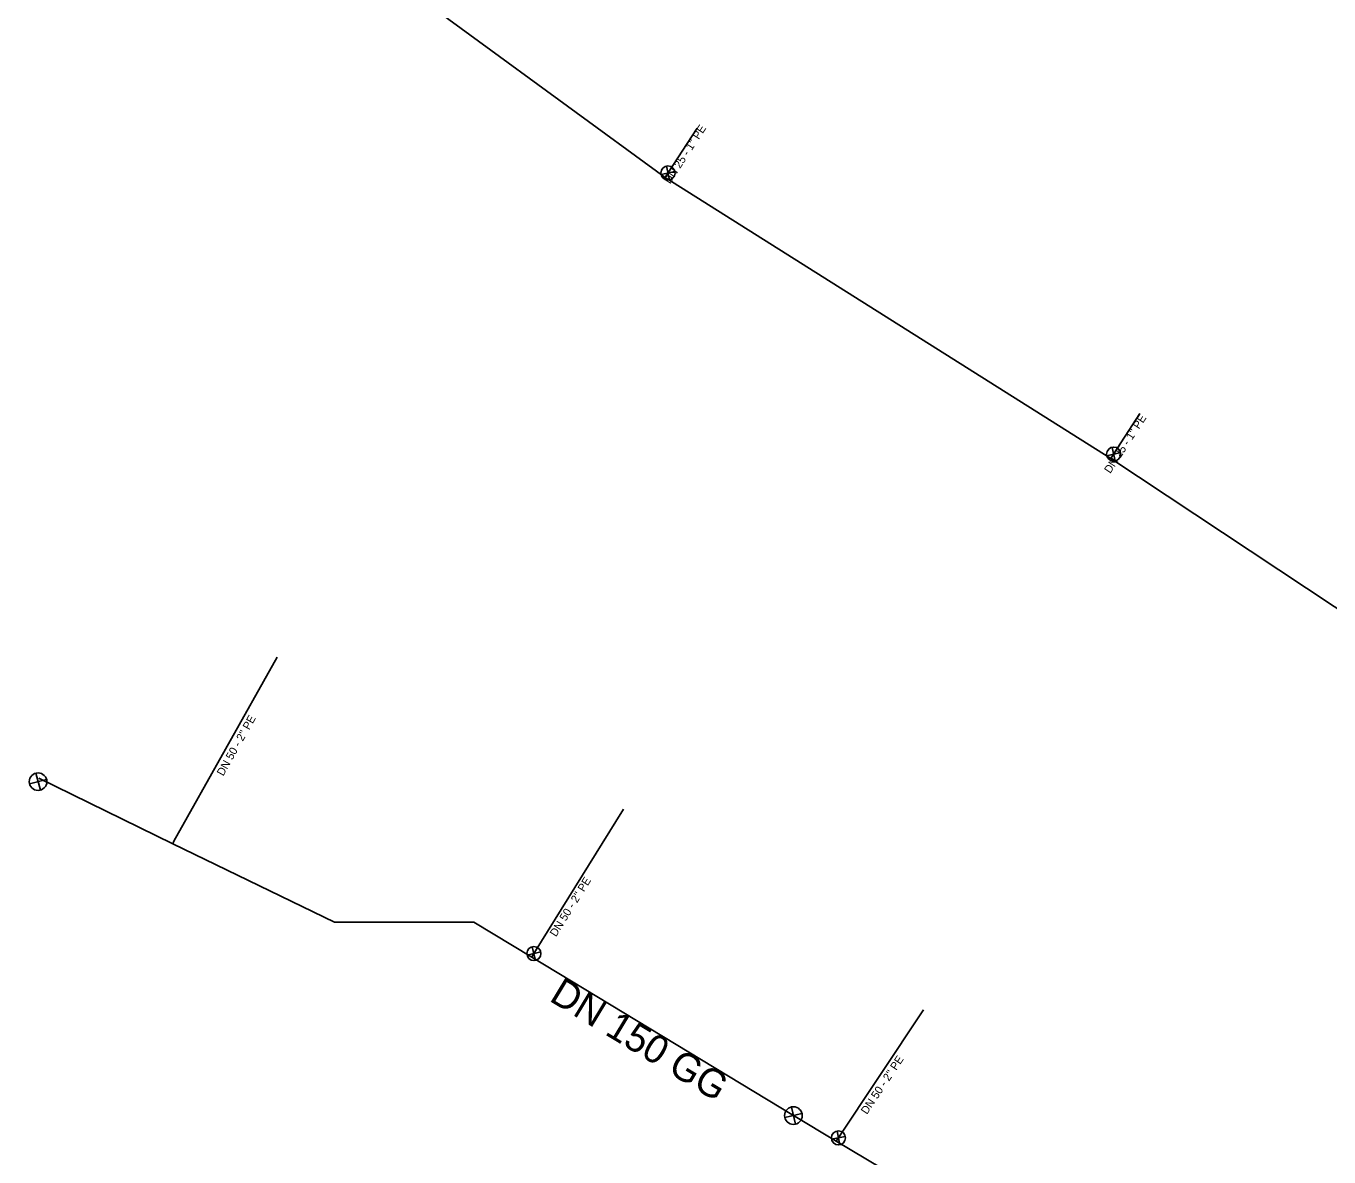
# Model space of a CAD drawing. Extents: x -443519 to -443021, y -1121477 to -1120870.
# Drawn here: x -443330.5 to -443256.5, y -1121307.3 to -1121243 of the extents above; entities that cross this region are included whole.
import ezdxf

# ---------------------------------------------------------------- set-up
doc = ezdxf.new("R2010")
doc.units = 0
for name, color, linetype in [('_pripojka_priblizne_', 7, 'Continuous'), ('_voda_smvak_prevzato_z_dokumentace_', 7, 'Continuous'), ('Default', 7, 'Continuous'), ('MoLevel 27', 7, 'Continuous'), ('MoLevel 32', 7, 'Continuous'), ('MoLevel 46', 7, 'Continuous'), ('MoLevel 53', 7, 'Continuous')]:
    doc.layers.add(name, color=color, linetype=linetype)

# ---------------------------------------------------------------- blocks, each defined once
blk = doc.blocks.new('_uzaver_')
at = {"layer": 'Default'}
for p, q in [((-0.000035, -0.000035), (0.000035, 0.000035)), ((0.000035, -0.000035), (-0.000035, 0.000035))]:
    blk.add_line(p, q, dxfattribs=at)
for radius in [0.00005, 0.0000025]:
    blk.add_circle((0, 0), radius, dxfattribs=at)
blk = doc.blocks.new('_uzaver_pripojka_')
at = {"layer": 'Default'}
for p, q in [((-0.000035, -0.000035), (0.000035, 0.000035)), ((0.000035, -0.000035), (-0.000035, 0.000035))]:
    blk.add_line(p, q, dxfattribs=at)
for radius in [0.00005, 0.0000025]:
    blk.add_circle((0, 0), radius, dxfattribs=at)

msp = doc.modelspace()

# ---------------------------------------------------------------- linework, layer by layer
at = {"layer": '_pripojka_priblizne_'}
msp.add_line((-443284.462, -1121306.393), (-443279.5, -1121298.935), dxfattribs=at)
for points in [[(-443294.198, -1121251.608), (-443294.03, -1121251.36), (-443292.38, -1121248.806)], [(-443268.857, -1121267.596), (-443268.7, -1121267.34), (-443267.205, -1121265.036)], [(-443322.17, -1121289.49), (-443322.11, -1121289.35), (-443316.238, -1121278.881)], [(-443301.769, -1121295.944), (-443301.65, -1121295.73), (-443296.563, -1121287.525)]]:
    msp.add_lwpolyline(points, dxfattribs=at)
at = {"layer": '_voda_smvak_prevzato_z_dokumentace_'}
for points in [[(-443310.841, -1121239.434), (-443294.198, -1121251.608), (-443268.857, -1121267.596), (-443245.045, -1121283.381), (-443235.625, -1121289.193)], [(-443329.78, -1121285.76), (-443322.17, -1121289.49), (-443312.974, -1121293.937), (-443305.072, -1121293.94), (-443301.769, -1121295.944), (-443286.9, -1121304.94)], [(-443286.9, -1121304.94), (-443284.462, -1121306.393), (-443265.875, -1121317.471), (-443257.965, -1121322.557)]]:
    msp.add_lwpolyline(points, dxfattribs=at)

# ---------------------------------------------------------------- block references
at = {"layer": 'MoLevel 27'}
for p, xscale, yscale, rotation in [((-443329.83, -1121285.96), 9999.999999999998, 10000.000000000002, -119.78029255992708), ((-443286.9, -1121304.94), 10000, 10000, -31.435966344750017)]:
    msp.add_blockref('_uzaver_', p, dxfattribs=dict(at, xscale=xscale, yscale=yscale, rotation=rotation))
at = {"layer": 'MoLevel 53', "xscale": 7999.999999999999}
for p, yscale, rotation in [((-443294.03, -1121251.36), 8000, 57.737039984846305), ((-443268.7, -1121267.34), 8000.000000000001, 57.953939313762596), ((-443301.65, -1121295.73), 7999.999999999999, 58.09350946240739), ((-443284.34, -1121306.21), 7999.999999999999, 56.370444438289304)]:
    msp.add_blockref('_uzaver_pripojka_', p, dxfattribs=dict(at, yscale=yscale, rotation=rotation))

# ---------------------------------------------------------------- texts
at = {"layer": 'MoLevel 32'}
for s, rotation, p in [("DN 25 - 1'' PE", 57.13471, (-443293.911, -1121252.014)), ("DN 25 - 1'' PE", 57.02141, (-443268.893, -1121268.473)), ("DN 50 - 2'' PE", 60.71366, (-443319.304, -1121285.672)), ("DN 50 - 2'' PE", 58.20159, (-443300.393, -1121294.81)), ("DN 50 - 2'' PE", 56.36512, (-443282.723, -1121304.905))]:
    msp.add_text(s, height=0.455, rotation=rotation, dxfattribs=at).set_placement(p)
at = {"layer": 'MoLevel 46'}
msp.add_text('DN 150 GG', height=1.6049, rotation=328.82647, dxfattribs=at).set_placement((-443300.839, -1121298.383))

doc.saveas('drawing.dxf')
